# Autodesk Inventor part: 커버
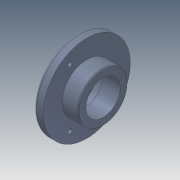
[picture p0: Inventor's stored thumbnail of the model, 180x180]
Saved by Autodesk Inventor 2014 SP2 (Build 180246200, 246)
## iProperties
Company: 한국ATC센터
Created: 2014-10
Part Number: 커버
Document SubType Name: Modeling
Designer: 한국ATC센터
Density: 2.71 g/cm^3
Material: 알루미늄-6061
Mass: 189.969 g
Surface Area: 197.235 cm^2
Volume: 70.0991 cm^3
Appearance: 슬레이트 파란색
Author: KYOUNG IL JANG
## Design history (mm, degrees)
sketch "스케치1"
  geometry: L1 (-13.5, 0)-(13.5, 0); L2 (-13.5, 0)-(-13.5, 45.5); L3 (-13.5, 45.5)-(-3.5, 45.5); L4 (-3.5, 45.5)-(-3.5, 26); L5 (-3.5, 26)-(13.5, 26); L6 (13.5, 26)-(13.5, 0); 2 further points
  constraints: 12 end point, 3 parallel, 2 perpendicular, 1 coincident, 1 horizontal, 1 midpoint
  dimensions: "d0" = 27 distance of L1.start L1.end; "d1" = 91 diameter of L3 L1; "d2" = 52 diameter of L5 L1; "d3" = 10 distance of L2.end L3.end
revolve "회전1" sketch "스케치1" stored, may be unused: angle "d4" = 90 deg
hole "구멍1" diameter "d7" = 36; stored, may be unused: countersink angle "d11" = 90 deg, drill point angle "d13" = 118 deg; dims "d5" = 10, "d6" = 10, "d8" = 6, "d9" = 40, "d10" = 8.3, "d12" = 8
sketch "스케치2"
  geometry: 2 further points
  constraints: 1 vertical alignment
  dimensions: "d14" = 35 distance of point (0, 0) point (0, 35)
hole "구멍2" sketch "스케치2" at (0, 35) diameter "d15" = 4.5; stored, may be unused: countersink angle "d19" = 90 deg, drill point angle "d21" = 118 deg; dims "d16" = 6, "d17" = 8, "d18" = 4.4, "d20" = 8
chamfer "모따기1" distance "d25" = 0.8; stored, may be unused: second distance "d26" = 2, angle "d27" = 30 deg
fillet "모깎기1" dims "d28" = 0.1, "d29" = 3
chamfer "모따기2" distance "d30" = 1; stored, may be unused: second distance "d31" = 2, angle "d32" = 30 deg
node "솔리드1"
pattern_circular "원형 패턴1" dims angle "d23" = 360 deg
